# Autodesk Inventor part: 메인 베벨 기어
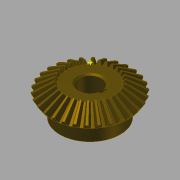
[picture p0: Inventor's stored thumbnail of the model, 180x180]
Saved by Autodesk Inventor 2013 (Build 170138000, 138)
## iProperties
Created: 2014-10
Part Number: 메인 베벨 기어
Material: 강철, 탄소
Document SubType Name: Modeling
Designer: KYOUNG IL JANG
Categories: <?xml version="1.0" encoding="UTF-16"?> <MemberInstance><Categories><FamilyTemplate><FamilyTemplateParameter ValueType="xs:double" Id="1" ObjectReferenceKey="da
Mass: 269.926 g
Surface Area: 108.837 cm^2
Volume: 34.2981 cm^3
Density: 7.87 g/cm^3
CustomPartVersion: 1
Author: SeoGD™ [www.esajin.kr]
Revision Number: 1
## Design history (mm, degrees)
node "맨 위 점"
node "메쉬 평면2"
sketch "톱니 본체 스케치"
  geometry: L1 (0, 0)-(28.669, -21.997); L2 (28.669, -21.997)-(31.109, -18.336); L3 (31.109, -18.336)-(0, 0); L4 (30, -20)-(0, 0); L5 (17.219, -13.212)-(18.685, -11.013); L6 (28.669, -21.997)-(17.219, -13.212); L7 (31.109, -18.336)-(18.685, -11.013); L8 (0, -39.387)-(0, 6.564) reference; L9 (0, -20)-(31.109, -20)
  constraints: 16 end point, 4 point on line, 3 perpendicular, 2 collinear, 1 horizontal alignment, 1 vertical alignment
  dimensions: "d0" = 60 diameter of L4.start L8 (= da_de); "d1" = 57.33744 diameter of L1.end L8 (= da_dfe); "d2" = 62.2188 diameter of L2.end L8 (= da_dae); "d3" = 14.4 distance between parallel lines of L2 L5 (= da_b); "d4" = 18.3359 vertical distance of L2.end L1.start (= da_ve)
revolve "톱니 본체" sketch "톱니 본체 스케치" stored, may be unused: angle "d5" = 90 deg
node "시작점"
node "톱니 평면"
sketch "시작 스케치"
  geometry: L1 (0, -23.505)-(0, 10.645) reference; L2 (-0.709, -2.928)-(0.709, -2.928); A1 r 19.188 centre (-19.457, -7.014) between (-0.709, -2.928) and (-3.232, 3.229); A2 r 19.188 centre (19.457, -7.014) between (3.232, 3.229) and (0.709, -2.928); A3 r 57.403 centre (0, -54.083) between (3.232, 3.229) and (-3.232, 3.229); 1 further point
  constraints: 6 point on circle, 3 centre point, 3 symmetric about line, 2 end point, 1 coincident, 1 perpendicular, 1 other
  dimensions: "d7" = 19.18795 radius of A1 (= fd_rr); "d8" = 19.45712 horizontal distance of point (0, -54.083) A1.centre (= fd_x); "d9" = 47.06905 vertical distance of point (0, -54.083) A1.centre (= fd_y); "d57" = 57.40327 radius of A3 (= 0.5 x fd_dva + 0.3 x da_he); "d58" = 51.15527 distance from line of A3.centre L2 (= 0.5 x fd_dva - 1.12 x da_he)
node "끝점"
  node "끝 평면"
sketch "3D 스케치 오른쪽"
  node "Helical Curve Right" dims "d65" = 229.90621 (computed from da_dm, da_delta, da_beta), "d66" = 31.5, "d67" = 60 (= da_de), "d68" = -9.82794 (= -da_delta), "d69" = 8.10972 (computed from fd_loft, da_delta)
node "끝 평면 오른쪽"
sketch "끝 스케치 오른쪽"
  geometry: L1 (0, -41.54)-(0, 13.178) reference; L2 (-0.422, -1.69)-(0.422, -1.69); A1 r 11.427 centre (-11.587, -4.123) between (-0.422, -1.69) and (-1.925, 1.977); A2 r 11.427 centre (11.587, -4.123) between (1.925, 1.977) and (0.422, -1.69); A3 r 34.184 centre (0, -32.153) between (1.925, 1.977) and (-1.925, 1.977); 1 further point
  constraints: 6 point on circle, 3 centre point, 3 symmetric about line, 2 end point, 1 coincident, 1 perpendicular, 1 other
  dimensions: "d70" = 11.58699 horizontal distance of A3.centre A1.centre (computed from fd_x, fd_ratio); "d71" = 28.03028 vertical distance of point (0, -32.153) A1.centre (computed from fd_y, fd_ratio); "d72" = 11.4267 radius of A1 (computed from fd_rr, fd_ratio); "d73" = 30.46369 distance from line of point (0, -32.153) L2 (computed from d58, fd_ratio); "d74" = 34.18446 radius of A3 (computed from d57, fd_ratio)
feature "로프트 오른쪽" sketch "끝 스케치 오른쪽" dims "d75" = 0, "d77" = 0, "d79" = 0, "d80" = 90 deg, "d85" = 20, "d92" = 90 deg, "d93" = 90 deg, "da_teethtype" = 0 [user parameter]
sketch "3D 스케치 왼쪽"
  node "Helical Curve Left" dims "d26" = 229.90621 (computed from da_dm, da_delta, da_beta), "d27" = 8.10972 (computed from fd_loft, da_delta), "d28" = 60 (= da_de), "d29" = -9.82794 (= -da_delta)
node "끝 평면 왼쪽"
sketch "끝 스케치 왼쪽" dims "d56" = 10.3728 (derived)
  geometry: L1 (0, -43.753)-(0, 15.405) reference; L2 (-0.422, -1.678)-(0.422, -1.678); A1 r 11.427 centre (-11.587, -4.111) between (-0.422, -1.678) and (-1.925, 1.988); A2 r 11.427 centre (11.587, -4.111) between (1.925, 1.988) and (0.422, -1.678); A3 r 34.184 centre (0, -32.142) between (1.925, 1.988) and (-1.925, 1.988); 2 further points; 1 other entity
  constraints: 6 point on circle, 3 centre point, 3 symmetric about line, 2 end point, 1 coincident, 2 other
  dimensions: "d30" = 11.4267 radius of A1 (computed from fd_rr, fd_ratio); "d31" = 11.58699 horizontal distance of point (0, -32.142) A1.centre (computed from fd_x, fd_ratio); "d32" = 28.03028 vertical distance of A1.centre point (0, -32.142) (computed from fd_y, fd_ratio); "d61" = 34.18446 radius of A3 (computed from d57, fd_ratio); "d62" = 30.46369 distance from line of point (0, -32.142) L2 (computed from d58, fd_ratio)
feature "로프트 왼쪽" sketch "끝 스케치 왼쪽" dims "d35" = 0, "d37" = 0, "d39" = 0, "d40" = 90 deg, "d84" = 10, "d90" = 90 deg, "d91" = 90 deg, "da_teethtype" = 0 [user parameter]
sketch "본체 스케치"
  geometry: L1 (0, -35.038)-(0, -19.531) reference; L2 (28.669, -21.997)-(17.219, -13.212) reference; L3 (17.219, -13.212)-(0, -13.212); L4 (28.669, -21.997)-(0, -21.997)
  constraints: 4 end point, 2 perpendicular, 2 point on line
revolve "본체 고정" sketch "본체 스케치" stored, may be unused: angle "d46" = 90 deg
feature "피치 지름" dims angle "d47" = 90 deg
sketch "스케치8"
  geometry: C1 r 22.5 at (0, 0); 1 further point
  constraints: 1 centre point, 1 coincident
  dimensions: "d94" = 45 diameter of C1
extrude "돌출1" join sketch "스케치8" distance "d95" = 13; taper "d96" = 0 deg
sketch "스케치9"
  geometry: 1 further point
hole "구멍1" sketch "스케치9" at (0, 0) diameter "d97" = 17; stored, may be unused: countersink angle "d101" = 90 deg, drill point angle "d103" = 118 deg; dims "d98" = 6, "d99" = 4, "d100" = 2, "d102" = 8
sketch "스케치10"
  geometry: L1 (8.124, 2.5)-(10.8, 2.5); L2 (10.8, 2.5)-(10.8, -2.5); L3 (10.8, -2.5)-(8.124, -2.5); A1 r 8.5 centre (0, 0) between (8.124, 2.5) and (8.124, -2.5) reference; 1 further point
  constraints: 6 end point, 2 parallel, 2 point on circle, 1 horizontal, 1 perpendicular
  dimensions: "d104" = 5 distance of L1.end L2.end; "d112" = 19.3 dimension on A1 L2
extrude "돌출2" cut sketch "스케치10" stored distance "d106" = 10; taper "d107" = 0 deg
chamfer "모따기1" distance "d108" = 1; stored, may be unused: second distance "d109" = 2, angle "d110" = 45 deg
fillet "모깎기1" dims "d111" = 2
body "Solid1"
feature "로프트" dims "d17" = 0, "d18" = 90 deg, "d19" = 0, "d20" = 90 deg, "d89" = 0, "da_teethtype" = 0 [user parameter]
pattern_circular "원형 패턴" dims angle "d22" = 360 deg, "d88" = 0, "da_teethtype" = 0 [user parameter]
pattern_circular "원형 패턴 오른쪽" dims angle "d82" = 360 deg, "da_teethtype" = 0 [user parameter]
pattern_circular "원형 패턴 왼쪽" dims angle "d42" = 360 deg, "da_teethtype" = 0 [user parameter]
sketch "끝 스케치"
  geometry: L1 (0, -15.359)-(0, 6.983) reference; L2 (-0.422, -1.69)-(0.422, -1.69); A1 r 11.427 centre (-11.587, -4.123) between (-0.422, -1.69) and (-1.925, 1.977); A2 r 11.427 centre (11.587, -4.123) between (1.925, 1.977) and (0.422, -1.69); A3 r 34.184 centre (0, -32.153) between (1.925, 1.977) and (-1.925, 1.977); 1 further point
  constraints: 6 point on circle, 3 centre point, 3 symmetric about line, 2 end point, 1 coincident, 1 other
  dimensions: "d12" = 11.4267 radius of A1 (computed from fd_rr, fd_ratio); "d15" = 11.58699 horizontal distance of A1.centre point (0, -32.153) (computed from fd_x, fd_ratio); "d16" = 28.03028 vertical distance of A1.centre point (0, -32.153) (computed from fd_y, fd_ratio); "d59" = 34.18446 radius of A3 (computed from d57, fd_ratio); "d60" = 30.46369 distance from line of A3.centre L2 (computed from d58, fd_ratio)
sketch "Sketch6"
  geometry: L1 (30, -20)-(0, 0) reference; L2 (0, -37.8)-(0, 6.3) reference
body "Srf1"
other parameters: "da_b" = 14.4 [user parameter; used in 2 equation terms], "da_de" = 60 [user parameter; used in 4 equation terms], "da_dae" = 62.2188 [user parameter; used in 2 equation terms], "da_dfe" = 57.33744 [user parameter; used in 1 equation term], "da_le" = 36.05551 [user parameter; used in 1 equation term], "da_omega" = 90 deg [user parameter; used in 1 equation term], "da_beta" = 0 [user parameter; used in 2 equation terms], "da_delta" = 9.82794 [user parameter; used in 8 equation terms], "da_alpha" = 20 deg [user parameter; used in 2 equation terms], "da_he" = 4.4 [user parameter; used in 4 equation terms], "da_ve" = 18.3359 [user parameter; used in 1 equation term], "fd_dv" = 108.16654 (computed from da_de, da_delta) [user parameter; used in 1 equation term], "fd_dva" = 112.16654 (computed from da_dae, da_delta) [user parameter; used in 3 equation terms], "fd_dvb" = 101.6433 (computed from fd_dv, da_alpha) [user parameter; used in 2 equation terms], "da_zv" = 540.83269 [user parameter; used in 1 equation term], "fd_loft" = 14.62 (= da_b + 0.05 x da_he) [user parameter; used in 4 equation terms], "fd_ratio" = 5.95514 (computed from da_le, fd_loft) [user parameter; used in 15 equation terms], "fd_rr" = 19.18795 (computed from fd_dd, fd_dvb) [user parameter; used in 6 equation terms], "fd_angle" = 0.29367 (computed from da_zv) [user parameter; used in 4 equation terms], "fd_x1" = 1.58802 (computed from da_dvw, fd_angle) [user parameter; used in 1 equation term], "fd_y1" = 54.05995 (computed from da_dvw, fd_angle) [user parameter; used in 1 equation term], "fd_x2" = 17.8691 (computed from fd_rr, fd_angle2, fd_angle) [user parameter; used in 1 equation term], "fd_y2" = 6.9909 (computed from fd_rr, fd_angle2, fd_angle) [user parameter; used in 1 equation term], "fd_x" = 19.45712 (= fd_x1 + fd_x2) [user parameter; used in 4 equation terms], "fd_y" = 47.06905 (= fd_y1 - fd_y2) [user parameter; used in 4 equation terms], "fd_angle2" = 3.43555 (computed from fd_dvb, fd_dd, da_alpha) [user parameter; used in 2 equation terms], "fd_dd" = 108.64654 (= fd_dva - 0.8 x da_he) [user parameter; used in 2 equation terms], "da_dvw" = 108.16654 [user parameter; used in 2 equation terms], "d11" = 14.62 (= fd_loft), "da_dm" = 48.01848 [user parameter; used in 2 equation terms], "da_x" = 0 [user parameter], "da_m" = 2 [user parameter], "d48" = 0, "d49" = 0, "d50" = 90 deg (= da_omega), "d51" = 6 deg (computed from da_z), "d52" = 0, "d53" = 0, "d54" = 0
